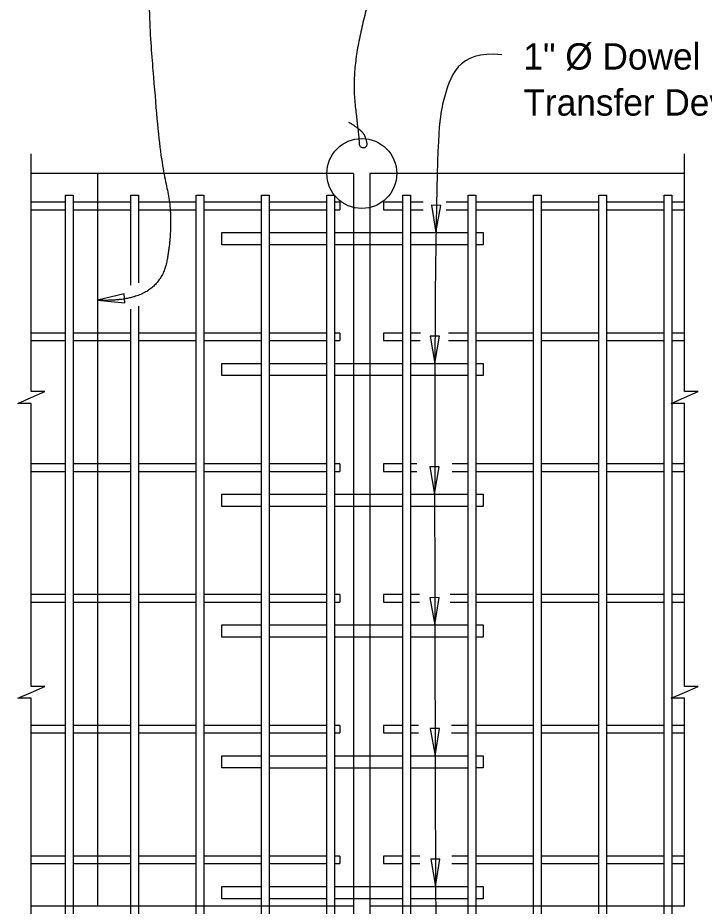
# Model space of a CAD drawing. Extents: x 120577.8 to 120649.9, y 120677.2 to 120721.6.
# Drawn here: x 120592.83 to 120598.08, y 120708.42 to 120715.22 of the extents above; entities that cross this region are included whole.
import ezdxf

# ---------------------------------------------------------------- set-up
doc = ezdxf.new("R2010")
doc.units = 0
for name, color, linetype in [('Patterning', 7, 'Continuous'), ('PlotBorder_dp', 7, 'Continuous'), ('TextMisc', 7, 'Continuous')]:
    doc.layers.add(name, color=color, linetype=linetype)

msp = doc.modelspace()

# ---------------------------------------------------------------- linework, layer by layer
at = {"layer": 'Patterning'}
for p, q in [((120593.1938, 120707.2437), (120593.1938, 120713.8614)), ((120593.1938, 120713.8614), (120593.2511, 120713.8614)), ((120593.2511, 120713.8614), (120593.2511, 120707.9744)), ((120593.6938, 120713.8614), (120593.7511, 120713.8614)), ((120593.6938, 120713.1732), (120593.6938, 120713.8614)), ((120593.7511, 120713.8614), (120593.7511, 120713.1916)), ((120594.1938, 120707.2437), (120594.1938, 120713.8614)), ((120594.1938, 120713.8614), (120594.2511, 120713.8614)), ((120594.2511, 120713.8614), (120594.2511, 120707.9744)), ((120594.6938, 120707.2437), (120594.6938, 120713.8614)), ((120594.6938, 120713.8614), (120594.7511, 120713.8614)), ((120594.7511, 120713.8614), (120594.7511, 120707.9744)), ((120595.1938, 120707.2437), (120595.1938, 120713.8614)), ((120595.1938, 120713.8614), (120595.2511, 120713.8614)), ((120595.2511, 120713.8614), (120595.2511, 120707.9744)), ((120595.7745, 120707.2437), (120595.7745, 120713.8614)), ((120595.7745, 120713.8614), (120595.8317, 120713.8614)), ((120595.8317, 120713.8614), (120595.8317, 120707.9744)), ((120596.2745, 120707.2437), (120596.2745, 120713.8614)), ((120596.2745, 120713.8614), (120596.3317, 120713.8614)), ((120596.3317, 120713.8614), (120596.3317, 120707.9744)), ((120596.7745, 120707.2437), (120596.7745, 120713.8614)), ((120596.7745, 120713.8614), (120596.8317, 120713.8614)), ((120596.8317, 120713.8614), (120596.8317, 120707.9744)), ((120597.2745, 120707.2437), (120597.2745, 120713.8614)), ((120597.2745, 120713.8614), (120597.3317, 120713.8614)), ((120597.3317, 120713.8614), (120597.3317, 120707.9744)), ((120597.7745, 120707.2437), (120597.7745, 120713.8614)), ((120597.7745, 120713.8614), (120597.8317, 120713.8614)), ((120597.8317, 120713.8614), (120597.8317, 120707.9744)), ((120595.2927, 120713.8067), (120595.2927, 120713.7494)), ((120595.6261, 120713.8067), (120595.6261, 120713.7494)), ((120593.6938, 120707.2437), (120593.6938, 120712.9884)), ((120593.7511, 120713.0131), (120593.7511, 120707.9744)), ((120595.2927, 120712.8067), (120595.2927, 120712.7494)), ((120595.6261, 120712.8067), (120595.6261, 120712.7494)), ((120595.2927, 120711.8067), (120595.2927, 120711.7494)), ((120595.6261, 120711.8067), (120595.6261, 120711.7494)), ((120595.2927, 120710.8067), (120595.2927, 120710.7494)), ((120595.6261, 120710.8067), (120595.6261, 120710.7494)), ((120595.2927, 120709.8067), (120595.2927, 120709.7494)), ((120595.6261, 120709.8067), (120595.6261, 120709.7494)), ((120595.2927, 120708.8067), (120595.2927, 120708.7494)), ((120595.6261, 120708.8067), (120595.6261, 120708.7494))]:
    msp.add_line(p, q, dxfattribs=at)
for points in [[(120593.1938, 120713.8067), (120592.9308, 120713.8067)], [(120593.6938, 120713.8067), (120593.2511, 120713.8067)], [(120594.1938, 120713.8067), (120593.7511, 120713.8067)], [(120594.6938, 120713.8067), (120594.2511, 120713.8067)], [(120595.1938, 120713.8067), (120594.7511, 120713.8067)], [(120595.2927, 120713.8067), (120595.2511, 120713.8067)], [(120595.7745, 120713.8067), (120595.6261, 120713.8067)], [(120595.9301, 120713.8067), (120595.8317, 120713.8067)], [(120596.2745, 120713.8067), (120596.1052, 120713.8067)], [(120596.7745, 120713.8067), (120596.3317, 120713.8067)], [(120597.2745, 120713.8067), (120596.8317, 120713.8067)], [(120597.7745, 120713.8067), (120597.3317, 120713.8067)], [(120597.9307, 120713.8067), (120597.8317, 120713.8067)], [(120592.9308, 120713.7494), (120593.1938, 120713.7494)], [(120593.2511, 120713.7494), (120593.6938, 120713.7494)], [(120593.7511, 120713.7494), (120594.1938, 120713.7494)], [(120594.2511, 120713.7494), (120594.6938, 120713.7494)], [(120594.7511, 120713.7494), (120595.1938, 120713.7494)], [(120595.2511, 120713.7494), (120595.2927, 120713.7494)], [(120595.6261, 120713.7494), (120595.7745, 120713.7494)], [(120595.8317, 120713.7494), (120595.9301, 120713.7494)], [(120596.1052, 120713.7494), (120596.2745, 120713.7494)], [(120596.3317, 120713.7494), (120596.7745, 120713.7494)], [(120596.8317, 120713.7494), (120597.2745, 120713.7494)], [(120597.3317, 120713.7494), (120597.7745, 120713.7494)], [(120597.8317, 120713.7494), (120597.9307, 120713.7494)], [(120594.3891, 120713.5749), (120594.6938, 120713.5749)], [(120594.6938, 120713.4812), (120594.3891, 120713.4812), (120594.3891, 120713.5749)], [(120594.7511, 120713.5749), (120595.1938, 120713.5749)], [(120595.2511, 120713.5749), (120595.7745, 120713.5749)], [(120595.8317, 120713.5749), (120596.2745, 120713.5749)], [(120596.3317, 120713.5749), (120596.3891, 120713.5749), (120596.3891, 120713.4812), (120596.3317, 120713.4812)], [(120595.1938, 120713.4812), (120594.7511, 120713.4812)], [(120595.7745, 120713.4812), (120595.2511, 120713.4812)], [(120596.2745, 120713.4812), (120595.8317, 120713.4812)], [(120593.1938, 120712.8067), (120592.9308, 120712.8067)], [(120593.6938, 120712.8067), (120593.2511, 120712.8067)], [(120594.1938, 120712.8067), (120593.7511, 120712.8067)], [(120594.6938, 120712.8067), (120594.2511, 120712.8067)], [(120595.1938, 120712.8067), (120594.7511, 120712.8067)], [(120595.2927, 120712.8067), (120595.2511, 120712.8067)], [(120595.7745, 120712.8067), (120595.6261, 120712.8067)], [(120595.9084, 120712.8067), (120595.8317, 120712.8067)], [(120596.2745, 120712.8067), (120596.1234, 120712.8067)], [(120596.7745, 120712.8067), (120596.3317, 120712.8067)], [(120597.2745, 120712.8067), (120596.8317, 120712.8067)], [(120597.7745, 120712.8067), (120597.3317, 120712.8067)], [(120597.9307, 120712.8067), (120597.8317, 120712.8067)], [(120592.9308, 120712.7494), (120593.1938, 120712.7494)], [(120593.2511, 120712.7494), (120593.6938, 120712.7494)], [(120593.7511, 120712.7494), (120594.1938, 120712.7494)], [(120594.2511, 120712.7494), (120594.6938, 120712.7494)], [(120594.7511, 120712.7494), (120595.1938, 120712.7494)], [(120595.2511, 120712.7494), (120595.2927, 120712.7494)], [(120595.6261, 120712.7494), (120595.7745, 120712.7494)], [(120595.8317, 120712.7494), (120595.9059, 120712.7494)], [(120596.1234, 120712.7494), (120596.2745, 120712.7494)], [(120596.3317, 120712.7494), (120596.7745, 120712.7494)], [(120596.8317, 120712.7494), (120597.2745, 120712.7494)], [(120597.3317, 120712.7494), (120597.7745, 120712.7494)], [(120597.8317, 120712.7494), (120597.9307, 120712.7494)], [(120594.3891, 120712.5749), (120594.6938, 120712.5749)], [(120594.6938, 120712.4812), (120594.3891, 120712.4812), (120594.3891, 120712.5749)], [(120594.7511, 120712.5749), (120595.1938, 120712.5749)], [(120595.2511, 120712.5749), (120595.7745, 120712.5749)], [(120595.8317, 120712.5749), (120596.2745, 120712.5749)], [(120596.3317, 120712.5749), (120596.3891, 120712.5749), (120596.3891, 120712.4812), (120596.3317, 120712.4812)], [(120595.1938, 120712.4812), (120594.7511, 120712.4812)], [(120595.7745, 120712.4812), (120595.2511, 120712.4812)], [(120596.2745, 120712.4812), (120595.8317, 120712.4812)], [(120593.1938, 120711.8067), (120592.9308, 120711.8067)], [(120593.6938, 120711.8067), (120593.2511, 120711.8067)], [(120594.1938, 120711.8067), (120593.7511, 120711.8067)], [(120594.6938, 120711.8067), (120594.2511, 120711.8067)], [(120595.1938, 120711.8067), (120594.7511, 120711.8067)], [(120595.2927, 120711.8067), (120595.2511, 120711.8067)], [(120595.7745, 120711.8067), (120595.6261, 120711.8067)], [(120595.8803, 120711.8067), (120595.8317, 120711.8067)], [(120596.2745, 120711.8067), (120596.1516, 120711.8067)], [(120596.7745, 120711.8067), (120596.3317, 120711.8067)], [(120597.2745, 120711.8067), (120596.8317, 120711.8067)], [(120597.7745, 120711.8067), (120597.3317, 120711.8067)], [(120597.9307, 120711.8067), (120597.8317, 120711.8067)], [(120592.9308, 120711.7494), (120593.1938, 120711.7494)], [(120593.2511, 120711.7494), (120593.6938, 120711.7494)], [(120593.7511, 120711.7494), (120594.1938, 120711.7494)], [(120594.2511, 120711.7494), (120594.6938, 120711.7494)], [(120594.7511, 120711.7494), (120595.1938, 120711.7494)], [(120595.2511, 120711.7494), (120595.2927, 120711.7494)], [(120595.6261, 120711.7494), (120595.7745, 120711.7494)], [(120595.8317, 120711.7494), (120595.8803, 120711.7494)], [(120596.1516, 120711.7494), (120596.2745, 120711.7494)], [(120596.3317, 120711.7494), (120596.7745, 120711.7494)], [(120596.8317, 120711.7494), (120597.2745, 120711.7494)], [(120597.3317, 120711.7494), (120597.7745, 120711.7494)], [(120597.8317, 120711.7494), (120597.9307, 120711.7494)], [(120594.3891, 120711.5749), (120594.6938, 120711.5749)], [(120594.6938, 120711.4812), (120594.3891, 120711.4812), (120594.3891, 120711.5749)], [(120594.7511, 120711.5749), (120595.1938, 120711.5749)], [(120595.2511, 120711.5749), (120595.7745, 120711.5749)], [(120595.8317, 120711.5749), (120596.2745, 120711.5749)], [(120596.3317, 120711.5749), (120596.3891, 120711.5749), (120596.3891, 120711.4812), (120596.3317, 120711.4812)], [(120595.1938, 120711.4812), (120594.7511, 120711.4812)], [(120595.7745, 120711.4812), (120595.2511, 120711.4812)], [(120596.2745, 120711.4812), (120595.8317, 120711.4812)], [(120593.1938, 120710.8067), (120592.9308, 120710.8067)], [(120593.6938, 120710.8067), (120593.2511, 120710.8067)], [(120594.1938, 120710.8067), (120593.7511, 120710.8067)], [(120594.6938, 120710.8067), (120594.2511, 120710.8067)], [(120595.1938, 120710.8067), (120594.7511, 120710.8067)], [(120595.2927, 120710.8067), (120595.2511, 120710.8067)], [(120595.7745, 120710.8067), (120595.6261, 120710.8067)], [(120595.9023, 120710.8067), (120595.8317, 120710.8067)], [(120596.2745, 120710.8067), (120596.1354, 120710.8067)], [(120596.7745, 120710.8067), (120596.3317, 120710.8067)], [(120597.2745, 120710.8067), (120596.8317, 120710.8067)], [(120597.7745, 120710.8067), (120597.3317, 120710.8067)], [(120597.9307, 120710.8067), (120597.8317, 120710.8067)], [(120592.9308, 120710.7494), (120593.1938, 120710.7494)], [(120593.2511, 120710.7494), (120593.6938, 120710.7494)], [(120593.7511, 120710.7494), (120594.1938, 120710.7494)], [(120594.2511, 120710.7494), (120594.6938, 120710.7494)], [(120594.7511, 120710.7494), (120595.1938, 120710.7494)], [(120595.2511, 120710.7494), (120595.2927, 120710.7494)], [(120595.6261, 120710.7494), (120595.7745, 120710.7494)], [(120595.8317, 120710.7494), (120595.9023, 120710.7494)], [(120596.1354, 120710.7494), (120596.2745, 120710.7494)], [(120596.3317, 120710.7494), (120596.7745, 120710.7494)], [(120596.8317, 120710.7494), (120597.2745, 120710.7494)], [(120597.3317, 120710.7494), (120597.7745, 120710.7494)], [(120597.8317, 120710.7494), (120597.9307, 120710.7494)], [(120594.3891, 120710.5749), (120594.6938, 120710.5749)], [(120594.6938, 120710.4812), (120594.3891, 120710.4812), (120594.3891, 120710.5749)], [(120594.7511, 120710.5749), (120595.1938, 120710.5749)], [(120595.2511, 120710.5749), (120595.7745, 120710.5749)], [(120595.8317, 120710.5749), (120596.2745, 120710.5749)], [(120596.3317, 120710.5749), (120596.3891, 120710.5749), (120596.3891, 120710.4812), (120596.3317, 120710.4812)], [(120595.1938, 120710.4812), (120594.7511, 120710.4812)], [(120595.7745, 120710.4812), (120595.2511, 120710.4812)], [(120596.2745, 120710.4812), (120595.8317, 120710.4812)], [(120593.1938, 120709.8067), (120592.9308, 120709.8067)], [(120593.6938, 120709.8067), (120593.2511, 120709.8067)], [(120594.1938, 120709.8067), (120593.7511, 120709.8067)], [(120594.6938, 120709.8067), (120594.2511, 120709.8067)], [(120595.1938, 120709.8067), (120594.7511, 120709.8067)], [(120595.2927, 120709.8067), (120595.2511, 120709.8067)], [(120595.7745, 120709.8067), (120595.6261, 120709.8067)], [(120595.8943, 120709.8067), (120595.8317, 120709.8067)], [(120596.2745, 120709.8067), (120596.1473, 120709.8067)], [(120596.7745, 120709.8067), (120596.3317, 120709.8067)], [(120597.2745, 120709.8067), (120596.8317, 120709.8067)], [(120597.7745, 120709.8067), (120597.3317, 120709.8067)], [(120597.9307, 120709.8067), (120597.8317, 120709.8067)], [(120592.9308, 120709.7494), (120593.1938, 120709.7494)], [(120593.2511, 120709.7494), (120593.6938, 120709.7494)], [(120593.7511, 120709.7494), (120594.1938, 120709.7494)], [(120594.2511, 120709.7494), (120594.6938, 120709.7494)], [(120594.7511, 120709.7494), (120595.1938, 120709.7494)], [(120595.2511, 120709.7494), (120595.2927, 120709.7494)], [(120595.6261, 120709.7494), (120595.7745, 120709.7494)], [(120595.8317, 120709.7494), (120595.8943, 120709.7494)], [(120596.1473, 120709.7494), (120596.2745, 120709.7494)], [(120596.3317, 120709.7494), (120596.7745, 120709.7494)], [(120596.8317, 120709.7494), (120597.2745, 120709.7494)], [(120597.3317, 120709.7494), (120597.7745, 120709.7494)], [(120597.8317, 120709.7494), (120597.9307, 120709.7494)], [(120594.3891, 120709.5749), (120594.6938, 120709.5749)], [(120594.6938, 120709.4812), (120594.3891, 120709.4812), (120594.3891, 120709.5749)], [(120594.7511, 120709.5749), (120595.1938, 120709.5749)], [(120595.2511, 120709.5749), (120595.7745, 120709.5749)], [(120595.8317, 120709.5749), (120596.2745, 120709.5749)], [(120596.3317, 120709.5749), (120596.3891, 120709.5749), (120596.3891, 120709.4812), (120596.3317, 120709.4812)], [(120594.7511, 120709.4812), (120595.1938, 120709.4812)], [(120595.2511, 120709.4812), (120595.7745, 120709.4812)], [(120595.8317, 120709.4812), (120596.2745, 120709.4812)], [(120593.1938, 120708.8067), (120592.9308, 120708.8067)], [(120592.9308, 120708.7494), (120593.1938, 120708.7494)], [(120593.6938, 120708.8067), (120593.2511, 120708.8067)], [(120593.2511, 120708.7494), (120593.6938, 120708.7494)], [(120594.1938, 120708.8067), (120593.7511, 120708.8067)], [(120593.7511, 120708.7494), (120594.1938, 120708.7494)], [(120594.6938, 120708.8067), (120594.2511, 120708.8067)], [(120594.2511, 120708.7494), (120594.6938, 120708.7494)], [(120595.1938, 120708.8067), (120594.7511, 120708.8067)], [(120594.7511, 120708.7494), (120595.1938, 120708.7494)], [(120595.2927, 120708.8067), (120595.2511, 120708.8067)], [(120595.2511, 120708.7494), (120595.2927, 120708.7494)], [(120595.7745, 120708.8067), (120595.6261, 120708.8067)], [(120595.6261, 120708.7494), (120595.7745, 120708.7494)], [(120595.9036, 120708.8067), (120595.8317, 120708.8067)], [(120595.8317, 120708.7494), (120595.9036, 120708.7494)], [(120596.2745, 120708.8067), (120596.15, 120708.8067)], [(120596.15, 120708.7494), (120596.2745, 120708.7494)], [(120596.7745, 120708.8067), (120596.3317, 120708.8067)], [(120596.3317, 120708.7494), (120596.7745, 120708.7494)], [(120597.2745, 120708.8067), (120596.8317, 120708.8067)], [(120596.8317, 120708.7494), (120597.2745, 120708.7494)], [(120597.7745, 120708.8067), (120597.3317, 120708.8067)], [(120597.3317, 120708.7494), (120597.7745, 120708.7494)], [(120597.9307, 120708.8067), (120597.8317, 120708.8067)], [(120597.8317, 120708.7494), (120597.9307, 120708.7494)], [(120594.3891, 120708.5749), (120594.6938, 120708.5749)], [(120594.6938, 120708.4812), (120594.3891, 120708.4812), (120594.3891, 120708.5749)], [(120594.7511, 120708.5749), (120595.1938, 120708.5749)], [(120595.2511, 120708.5749), (120595.7745, 120708.5749)], [(120595.8317, 120708.5749), (120596.2745, 120708.5749)], [(120596.3317, 120708.5749), (120596.3891, 120708.5749), (120596.3891, 120708.4812), (120596.3317, 120708.4812)], [(120595.1938, 120708.4812), (120594.7511, 120708.4812)], [(120595.7745, 120708.4812), (120595.2511, 120708.4812)], [(120596.2745, 120708.4812), (120595.8317, 120708.4812)]]:
    msp.add_lwpolyline(points, dxfattribs=at)
at = {"layer": 'PlotBorder_dp'}
for points in [[(120592.9307, 120710.7494), (120592.9307, 120712.2689), (120592.8274, 120712.2689), (120592.9307, 120712.3139), (120593.0341, 120712.3589), (120592.9307, 120712.3589), (120592.9307, 120714.178)], [(120597.9307, 120710.7494), (120597.9307, 120712.2689), (120597.8274, 120712.2689), (120597.9307, 120712.3139), (120598.0341, 120712.3589), (120597.9307, 120712.3589), (120597.9307, 120714.178)], [(120592.9307, 120708.4239), (120592.9307, 120710.0138), (120592.8274, 120710.0138), (120592.9307, 120710.0588), (120593.0341, 120710.1038), (120592.9307, 120710.1038), (120592.9307, 120710.7494)], [(120597.9307, 120708.4239), (120597.9307, 120710.0138), (120597.8274, 120710.0138), (120597.9307, 120710.0588), (120598.0341, 120710.1038), (120597.9307, 120710.1038), (120597.9307, 120710.7494)], [(120592.9308, 120708.189), (120592.9308, 120708.4238)]]:
    msp.add_lwpolyline(points, dxfattribs=at)
for points in [[(120596.0265, 120713.5748), (120596.065, 120713.7825), (120595.9945, 120713.7836)], [(120593.4369, 120713.059), (120593.647, 120713.0371), (120593.6424, 120713.1075)], [(120596.0189, 120712.5749), (120596.055, 120712.783), (120595.9845, 120712.7833)], [(120596.0173, 120711.5749), (120596.051, 120711.7834), (120595.9805, 120711.7829)], [(120596.0184, 120710.5749), (120596.0521, 120710.7834), (120595.9816, 120710.7829)], [(120596.021, 120709.5749), (120596.0547, 120709.7834), (120595.9841, 120709.7829)], [(120596.0246, 120708.5749), (120596.0583, 120708.7834), (120595.9877, 120708.7829)]]:
    msp.add_lwpolyline(points, close=True, dxfattribs=at)
msp.add_circle((120595.46, 120714.0269), 0.2674, dxfattribs=at)
for points, degree in [([(120594.8356, 120716.493), (120593.7598, 120716.5315), (120593.8917, 120714.2273), (120594.0299, 120713.6832), (120593.907, 120713.0325), (120593.4369, 120713.059)], 2), ([(120595.9949, 120715.783), (120595.6732, 120715.8372), (120595.4752, 120715.2462), (120595.3839, 120714.7433), (120595.4397, 120714.3013), (120595.4397, 120714.2251), (120595.5006, 120714.2251), (120595.5006, 120714.2759), (120595.4651, 120714.3572), (120595.361, 120714.4181)], 2), ([(120596.5315, 120714.934), (120596.1932, 120714.9722), (120596.07, 120714.5664), (120595.9987, 120714.1931), (120596.0289, 120707.5749)], 3)]:
    msp.add_open_spline(points, degree=degree, dxfattribs=at)
at = {"layer": 'TextMisc'}
for p, q in [((120595.3969, 120714.028), (120592.9308, 120714.028)), ((120593.4369, 120714.028), (120593.4369, 120708.4238)), ((120595.3969, 120714.028), (120595.3969, 120707.0072)), ((120595.5219, 120714.028), (120595.5219, 120707.0072)), ((120597.9308, 120714.028), (120595.5219, 120714.028)), ((120595.3969, 120708.4238), (120592.9308, 120708.4238)), ((120597.9308, 120708.4238), (120595.5219, 120708.4238))]:
    msp.add_line(p, q, dxfattribs=at)

# ---------------------------------------------------------------- texts
at = {"layer": 'PlotBorder_dp'}
for s, p in [('1" Ø Dowel Load ', (120596.697, 120714.8216)), ('Transfer Devices ', (120596.697, 120714.4696))]:
    msp.add_text(s, height=0.2016, dxfattribs=at).set_placement(p)

doc.saveas('drawing.dxf')
